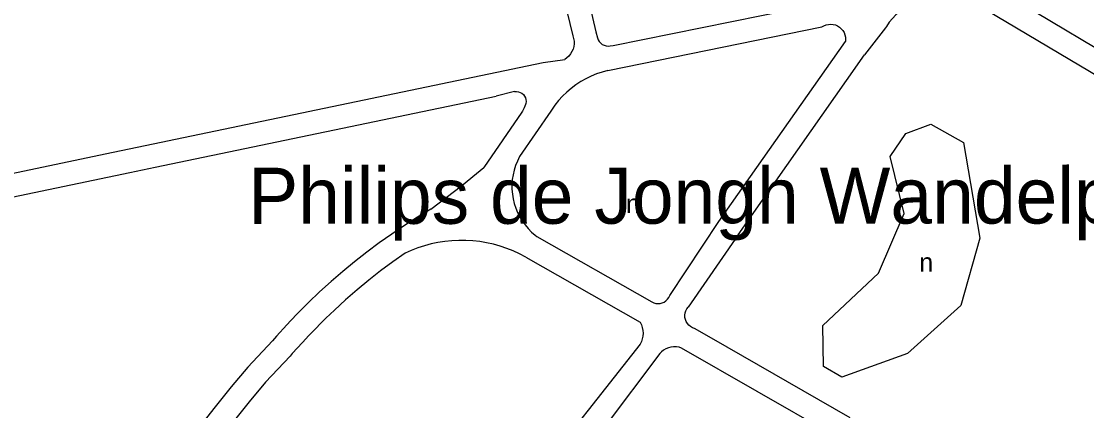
# Model space of a CAD drawing. Extents: x 157155 to 159285, y 385001 to 386651.
# Drawn here: x 158780.5 to 159008.3, y 385315.8 to 385399.2 of the extents above; entities that cross this region are included whole.
import ezdxf

# ---------------------------------------------------------------- set-up
doc = ezdxf.new("R2010")
doc.units = 0
for name, color, linetype in [('BLT_Basislijn', 7, 'Continuous'), ('BLT_Centroide', 7, 'Continuous'), ('BLT_Sport_parknaam', 7, 'Continuous')]:
    doc.layers.add(name, color=color, linetype=linetype)

msp = doc.modelspace()

# ---------------------------------------------------------------- linework, layer by layer
at = {"layer": 'BLT_Basislijn'}
for p, q in [((158886.71, 385444.19), (158898.45, 385396.07)), ((158892.69, 385442.52), (158903.39, 385396.93)), ((158907.07, 385394.01), (158959.9, 385404.76)), ((159045.49, 385366.59), (158984.59, 385402.96)), ((159048.05, 385370.89), (158997.45, 385401.11)), ((158903.39, 385396.93), (158903.7, 385395.63)), ((158905.9, 385388.67), (158951.71, 385397.99)), ((158965.29, 385397.8), (158960.81, 385392.02)), ((158906.41, 385393.92), (158907.07, 385394.01)), ((158929.69, 385356.34), (158956.72, 385394.89)), ((158956.96, 385386.52), (158960.81, 385392.02)), ((158805.27, 385372.25), (158892.12, 385390.38)), ((158892.12, 385390.38), (158896.71, 385391.05)), ((158933.78, 385353.47), (158956.96, 385386.52)), ((158809.12, 385367.95), (158882.03, 385383.17)), ((158885.98, 385384.16), (158882.03, 385383.17)), ((158893.75, 385379.99), (158887.05, 385370.23)), ((158887.51, 385379.74), (158879.38, 385367.9)), ((158749.19, 385360.54), (158800.11, 385371.17)), ((158800.11, 385371.17), (158805.27, 385372.25)), ((158750.22, 385355.65), (158803.67, 385366.81)), ((158803.67, 385366.81), (158809.12, 385367.95)), ((158919.19, 385340.53), (158929.69, 385356.34)), ((158890.76, 385353.12), (158915.3, 385339.13)), ((158933.78, 385353.47), (158923.07, 385338.04)), ((158888.38, 385348.72), (158912.83, 385334.78)), ((158928.1, 385331.36), (158924.48, 385333.43)), ((158834.19, 385330.82), (158828.89, 385325.2)), ((158912.82, 385330.12), (158901.7, 385315.97)), ((158957.77, 385314.36), (158928.1, 385331.36)), ((158837.97, 385327.55), (158832.71, 385321.98)), ((158917.02, 385328.1), (158905.11, 385312.23)), ((158959.82, 385307.43), (158921.7, 385329.26))]:
    msp.add_line(p, q, dxfattribs=at)
for points in [[(158984.59, 385402.96), (158983.62, 385403.44), (158982.61, 385403.84), (158981.58, 385404.16), (158980.53, 385404.41), (158979.46, 385404.58), (158978.39, 385404.67), (158977.3, 385404.68), (158976.23, 385404.62), (158975.15, 385404.47), (158974.1, 385404.24), (158973.06, 385403.94), (158972.05, 385403.55), (158971.07, 385403.1), (158970.12, 385402.58), (158969.22, 385401.98), (158968.36, 385401.32), (158967.55, 385400.6), (158966.8, 385399.82), (158966.11, 385398.99), (158965.49, 385398.11), (158965.29, 385397.8)], [(158951.71, 385397.99), (158952.14, 385398.25), (158952.61, 385398.44), (158953.1, 385398.55), (158953.6, 385398.59), (158954.11, 385398.54), (158954.6, 385398.42), (158955.06, 385398.22), (158955.49, 385397.94), (158955.86, 385397.61), (158956.18, 385397.22), (158956.44, 385396.78), (158956.62, 385396.31), (158956.73, 385395.82), (158956.76, 385395.31), (158956.72, 385394.89)], [(158898.45, 385396.07), (158898.61, 385395.52), (158898.7, 385394.95), (158898.7, 385394.37), (158898.63, 385393.8), (158898.48, 385393.24), (158898.25, 385392.71), (158897.95, 385392.21), (158897.59, 385391.76), (158897.17, 385391.37), (158896.71, 385391.05)], [(158903.7, 385395.63), (158903.86, 385395.22), (158904.09, 385394.85), (158904.39, 385394.52), (158904.74, 385394.26), (158905.14, 385394.06), (158905.56, 385393.93), (158906, 385393.89), (158906.41, 385393.92)], [(158905.9, 385388.67), (158904.69, 385388.35), (158903.5, 385387.94), (158902.34, 385387.46), (158901.21, 385386.91), (158900.12, 385386.29), (158899.08, 385385.6), (158898.08, 385384.85), (158897.12, 385384.03), (158896.23, 385383.15), (158895.39, 385382.22), (158894.61, 385381.24), (158893.89, 385380.21), (158893.75, 385379.99)], [(158885.98, 385384.16), (158886.39, 385384.18), (158886.8, 385384.12), (158887.19, 385383.99), (158887.54, 385383.79), (158887.85, 385383.51), (158888.1, 385383.19), (158888.28, 385382.82), (158888.39, 385382.43), (158888.42, 385382.02), (158888.37, 385381.61), (158888.32, 385381.41)], [(158888.32, 385381.41), (158888.02, 385380.67), (158887.65, 385379.96), (158887.51, 385379.74)], [(158887.05, 385370.23), (158886.59, 385369.3), (158886.2, 385368.34), (158885.89, 385367.36), (158885.65, 385366.35), (158885.49, 385365.33), (158885.42, 385364.3), (158885.42, 385363.26), (158885.5, 385362.23), (158885.67, 385361.21), (158885.91, 385360.21), (158886.23, 385359.22), (158886.62, 385358.27), (158887.08, 385357.34), (158887.62, 385356.46), (158888.22, 385355.62), (158888.89, 385354.83), (158889.61, 385354.09), (158890.39, 385353.41), (158890.76, 385353.12)], [(158868.06, 385359), (158871.37, 385361.48), (158874.63, 385364.02), (158877.84, 385366.62), (158879.38, 385367.9)], [(158868.06, 385359), (158865.23, 385357.29), (158862.45, 385355.52), (158859.71, 385353.67), (158857.01, 385351.76), (158854.36, 385349.79), (158851.76, 385347.75), (158849.21, 385345.65), (158846.72, 385343.49), (158844.27, 385341.27), (158841.88, 385338.99), (158841.72, 385338.82)], [(158888.38, 385348.72), (158887.06, 385349.42), (158885.7, 385350.05), (158884.31, 385350.6), (158882.9, 385351.08), (158881.46, 385351.48), (158880, 385351.81), (158878.52, 385352.05), (158877.03, 385352.22), (158875.54, 385352.31), (158874.05, 385352.31), (158872.55, 385352.24), (158871.06, 385352.09), (158869.59, 385351.86), (158868.12, 385351.55), (158866.68, 385351.16), (158865.26, 385350.69), (158863.86, 385350.15), (158862.57, 385349.58)], [(158862.57, 385349.58), (158859.93, 385347.7), (158857.33, 385345.76), (158854.78, 385343.76), (158852.28, 385341.7), (158849.83, 385339.57), (158847.44, 385337.38), (158845.62, 385335.64)], [(158841.72, 385338.82), (158839.55, 385336.65), (158838.14, 385335.17)], [(158915.3, 385339.13), (158915.73, 385338.93), (158916.17, 385338.81), (158916.64, 385338.77), (158917.1, 385338.81), (158917.55, 385338.92), (158917.98, 385339.11), (158918.36, 385339.38), (158918.7, 385339.7), (158918.97, 385340.08), (158919.19, 385340.53)], [(158924.48, 385333.43), (158924.03, 385333.6), (158923.62, 385333.84), (158923.25, 385334.14), (158922.94, 385334.51), (158922.69, 385334.92), (158922.52, 385335.36), (158922.42, 385335.83), (158922.4, 385336.31), (158922.46, 385336.78), (158922.59, 385337.24), (158922.81, 385337.67), (158923.07, 385338.04)], [(158838.14, 385335.17), (158837.27, 385334.26), (158835.06, 385331.81), (158834.19, 385330.82)], [(158845.62, 385335.64), (158845.1, 385335.14), (158842.82, 385332.84), (158841.98, 385331.95)], [(158912.83, 385334.78), (158913.1, 385334.23), (158913.29, 385333.65), (158913.41, 385333.05), (158913.45, 385332.44), (158913.4, 385331.83), (158913.28, 385331.23), (158913.09, 385330.65), (158912.82, 385330.12)], [(158841.98, 385331.95), (158840.59, 385330.48), (158838.43, 385328.07), (158837.97, 385327.55)], [(158921.7, 385329.26), (158921.15, 385329.43), (158920.58, 385329.53), (158920, 385329.54), (158919.43, 385329.48), (158918.87, 385329.33), (158918.33, 385329.11), (158917.83, 385328.82), (158917.38, 385328.47), (158917.02, 385328.1)], [(158828.89, 385325.2), (158825.37, 385320.96), (158821.91, 385316.67), (158818.52, 385312.33), (158815.18, 385307.94), (158811.92, 385303.5), (158808.71, 385299.02), (158807.03, 385296.58)], [(158832.71, 385321.98), (158829.21, 385317.77), (158825.78, 385313.5), (158822.41, 385309.19), (158819.1, 385304.83), (158815.86, 385300.42), (158812.68, 385295.97), (158810.18, 385292.34)], [(158901.7, 385315.97), (158900.35, 385314.27), (158899.07, 385312.53), (158897.85, 385310.74), (158896.69, 385308.91), (158895.87, 385307.5)]]:
    msp.add_lwpolyline(points, dxfattribs=at)
msp.add_lwpolyline([(158966.33, 385370.26), (158969.67, 385375.22), (158974.97, 385377.18), (158982, 385373.26), (158985.45, 385352.75), (158981.42, 385338.35), (158970.02, 385328.1), (158955.96, 385323.03), (158952.04, 385325.33), (158951.93, 385334.09), (158963.79, 385345.26), (158969.32, 385358.05)], close=True, dxfattribs=at)

# ---------------------------------------------------------------- texts
at = {"layer": 'BLT_Centroide'}
for p in [(158909.79, 385358.18), (158972.53, 385345.61)]:
    msp.add_text('n', height=4, dxfattribs=at).set_placement(p)
at = {"layer": 'BLT_Sport_parknaam'}
msp.add_text('Philips de Jongh Wandelpark', height=12, rotation=0.0206, dxfattribs=at).set_placement((158829, 385355.85))

doc.saveas('drawing.dxf')
